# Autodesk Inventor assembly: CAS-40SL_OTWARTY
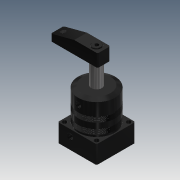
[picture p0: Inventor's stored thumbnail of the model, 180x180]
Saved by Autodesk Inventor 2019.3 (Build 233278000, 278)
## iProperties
Created: 2009-09
Part Number: CAS-40SL_OTWARTY
Material: Ogólny
Document SubType Name: Assembly
Designer: CADENGINEERING4
Sending System: PRO/ENGINEER BY PARAMETRIC TECHNOLOGY CORPORATION, 2007170
Preprocessor: PRO/ENGINEER BY PARAMETRIC TECHNOLOGY CORPORATION, 2007170
Title: CAS-40S_ASM
Author: Administrator
Revision Number: 2LAST_VERSION
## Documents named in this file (7)
- D:\Vault_2016\Projekty\STRONA\Pneumatic\Line ; Pipe connecct - type\cas-40s_asm\CAS-40SL_OTWARTY.iam
- D:\Vault_2016\Projekty\STRONA\Pneumatic\Line ; Pipe connecct - type\cas-40s_asm\CAS-40BT.ipt
- D:\Vault_2016\Projekty\STRONA\Pneumatic\Line ; Pipe connecct - type\cas-40s_asm\CAS-40HSG.ipt
- D:\Vault_2016\Projekty\STRONA\Pneumatic\Line ; Pipe connecct - type\cas-40s_asm\CAS-40HG.ipt
- D:\Vault_2016\Projekty\STRONA\Pneumatic\Line ; Pipe connecct - type\cas-40s_asm\M4.ipt
- D:\Vault_2016\Projekty\STRONA\Pneumatic\Line ; Pipe connecct - type\cas-40s_asm\CAS-32SYB.ipt
- D:\Vault_2016\Projekty\STRONA\Pneumatic\Line ; Pipe connecct - type\cas-40s_asm\M8LC.ipt
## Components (9 placed, 9 different names)
1. CAS-40BT_0 — Kątowe:1
2. CAS-40HSG_1 — Zestawiające:1, Zestawiające:2
3. CAS-40HG_2
4. M4_3
5. M4_4
6. M4_5
7. M4_6
8. CAS-32SYB_7 — Zestawiające:1, Zestawiające:2, Kątowe:1
9. M8LC_8
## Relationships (3: Mate 2, Angle 1)
- Zestawiające:1 [Mate]: CAS-40HSG_1 ↔ CAS-32SYB_7
- Zestawiające:2 [Mate]: CAS-40HSG_1 ↔ CAS-32SYB_7
- Kątowe:1 [Angle]: CAS-40BT_0 ↔ CAS-32SYB_7
